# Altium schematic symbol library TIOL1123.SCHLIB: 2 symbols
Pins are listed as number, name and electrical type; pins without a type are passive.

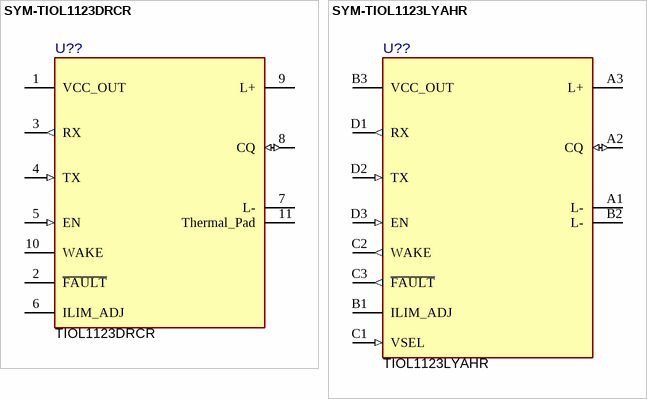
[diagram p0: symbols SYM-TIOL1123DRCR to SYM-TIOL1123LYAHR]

## SYM-TIOL1123DRCR
designator U??, comment TIOL1123DRCR
IO-Link Device Transceiver with Low Residual Voltage and Integrated Surge Protection, VSON10; Manufacturer: Texas Instruments; TaMin_C: -40°C; Min Supply Voltage: 7V; Standoff Height: 0mm; TaMax_C: +125°C; Interface: Other; TJmax_C: +150°C; Max Supply Voltage: 36V; AEC Qualified: No; SizeZ_mm: 1mm; Nominal Supply Current: 1-2mA
footprint DRC0010V-MFG
pins: 1 VCC_OUT (power), 2 ~{FAULT} (oc), 3 RX (out), 4 TX (in), 5 EN (in), 6 ILIM_ADJ, 7 L- (power), 8 CQ (io), 9 L+ (power), 10 WAKE (oc), 11 Thermal_Pad (power)

## SYM-TIOL1123LYAHR
designator U??, comment TIOL1123LYAHR
IO-Link Device Transceivers with Low Residual Voltage and Integrated Surge Protection; Manufacturer: Texas Instruments; TJmax_C: +150°C; Interface: Other; TaMax_C: +125°C; AEC Qualified: No; Min Supply Voltage: 3V; Nominal Supply Current: 1-2mA; Standoff Height: 0.11mm; Max Supply Voltage: 36V; TaMin_C: -40°C; SizeZ_mm: 0.4mm
footprint YAH0012-C01-MFG
footprint YAH0012-C01-IPC_C
footprint YAH0012-C01-IPC_B
footprint YAH0012-C01-IPC_A
pins: A1 L- (power), A2 CQ (io), A3 L+ (power), B1 ILIM_ADJ, B2 L- (power), B3 VCC_OUT (power), C1 VSEL (in), C2 WAKE (out), C3 ~{FAULT} (out), D1 RX (out), D2 TX (in), D3 EN (in)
